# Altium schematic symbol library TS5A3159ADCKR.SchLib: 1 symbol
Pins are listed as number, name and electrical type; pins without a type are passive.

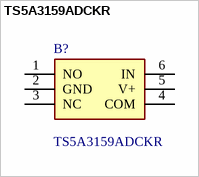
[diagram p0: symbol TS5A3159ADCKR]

## TS5A3159ADCKR
designator B?
1 Ohm SPDT Analog Switch 5-V/3.3-V Single Channel 2:1 Multiplexer/Demultiplexer; Manufacturer_Name: Texas Instruments; Geometry.Height: 1.1mm
footprint SOT65P210X110-6N
pins: 1 NO, 2 GND, 3 NC, 4 COM, 5 V+, 6 IN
